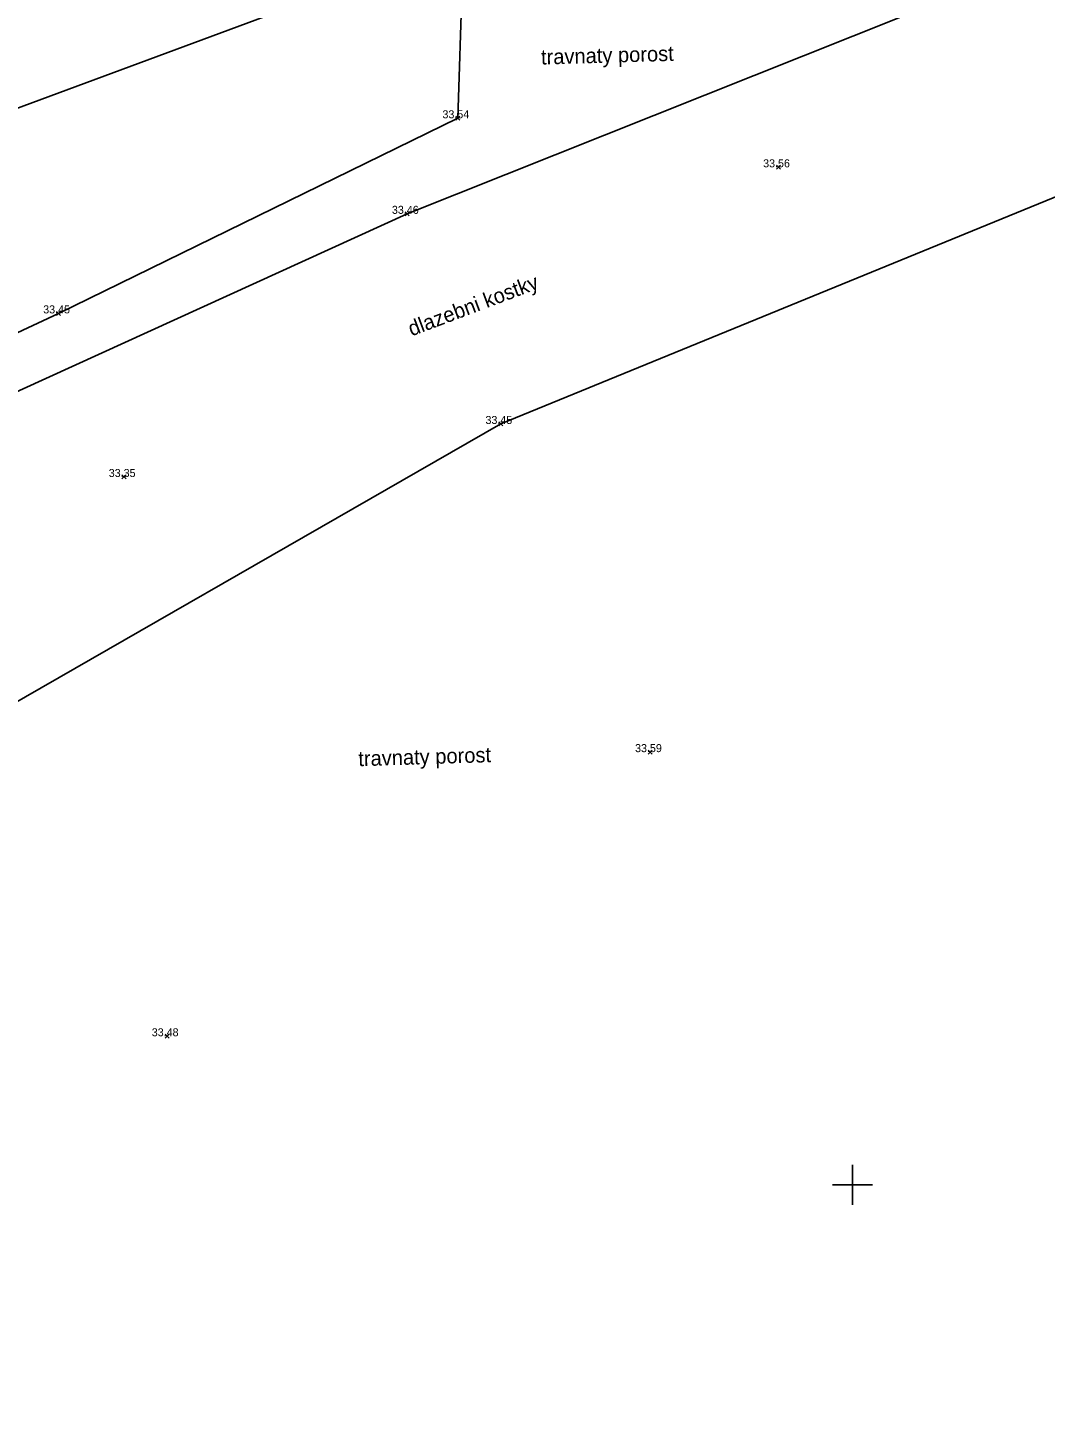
# Model space of a CAD drawing. Extents: x -772865 to -772533, y -1034366 to -1034132.
# Drawn here: x -772791.49 to -772771.14, y -1034304.37 to -1034276.87 of the extents above; entities that cross this region are included whole.
import ezdxf

# ---------------------------------------------------------------- set-up
doc = ezdxf.new("R2010")
doc.units = 0
for name, color, linetype in [('body', 7, 'Continuous'), ('KM_hranice', 7, 'Continuous'), ('mistni_popis', 7, 'Continuous'), ('oddeleni_ploch', 7, 'Continuous'), ('souradnicova_sit', 7, 'Continuous'), ('stromy_kere', 7, 'Continuous'), ('vyskove_koty', 7, 'Continuous')]:
    doc.layers.add(name, color=color, linetype=linetype)

msp = doc.modelspace()

# ---------------------------------------------------------------- linework, layer by layer
at = {"layer": 'body'}
for p, q in [((-772782.85, -1034278.72), (-772782.93, -1034278.64)), ((-772782.93, -1034278.72), (-772782.85, -1034278.64)), ((-772776.44, -1034279.7), (-772776.52, -1034279.62)), ((-772776.52, -1034279.7), (-772776.44, -1034279.62)), ((-772783.86, -1034280.63), (-772783.94, -1034280.55)), ((-772783.94, -1034280.63), (-772783.86, -1034280.55)), ((-772790.83, -1034282.62), (-772790.91, -1034282.54)), ((-772790.91, -1034282.62), (-772790.83, -1034282.54)), ((-772781.99, -1034284.83), (-772782.07, -1034284.75)), ((-772782.07, -1034284.83), (-772781.99, -1034284.75)), ((-772789.52, -1034285.89), (-772789.6, -1034285.81)), ((-772789.6, -1034285.89), (-772789.52, -1034285.81)), ((-772779, -1034291.39), (-772779.08, -1034291.31)), ((-772779.08, -1034291.39), (-772779, -1034291.31)), ((-772788.66, -1034297.07), (-772788.74, -1034296.99)), ((-772788.74, -1034297.07), (-772788.66, -1034296.99))]:
    msp.add_line(p, q, dxfattribs=at)
at = {"layer": 'KM_hranice'}
msp.add_line((-772778.45, -1034273.57), (-772798.72, -1034281.08), dxfattribs=at)
at = {"layer": 'oddeleni_ploch'}
for points in [[(-772569.67, -1034207.72), (-772578.35, -1034211.18), (-772588.33, -1034216.15), (-772592.11, -1034217.46), (-772598.89, -1034219.1), (-772610.21, -1034219.57), (-772621.14, -1034219.48), (-772637.34, -1034221.06), (-772647.54, -1034222.08), (-772674.34, -1034233.24), (-772685.01, -1034239.21), (-772697.33, -1034242.95), (-772712.12, -1034249.56), (-772725.85, -1034254.8), (-772738.85, -1034261.98), (-772750.37, -1034267.76), (-772764, -1034272.65), (-772783.9, -1034280.59), (-772796.38, -1034286.28), (-772810.31, -1034291.67), (-772823.61, -1034294.35), (-772828.52, -1034296.12), (-772827.01, -1034302.81), (-772823.23, -1034300.75)], [(-772689.63, -1034259.88), (-772704.53, -1034266.45), (-772719.18, -1034273.09), (-772731.59, -1034278.63), (-772738.33, -1034281.57), (-772742.46, -1034279.19), (-772747.03, -1034275.55), (-772755.44, -1034275.22), (-772763.58, -1034277.24), (-772782.03, -1034284.79), (-772793.82, -1034291.56), (-772799.88, -1034296.39), (-772802.42, -1034299.52), (-772804.8, -1034304.37)]]:
    msp.add_lwpolyline(points, dxfattribs=at)
at = {"layer": 'souradnicova_sit'}
for p, q in [((-772775, -1034299.6), (-772775, -1034300.4)), ((-772775.4, -1034300), (-772774.6, -1034300))]:
    msp.add_line(p, q, dxfattribs=at)
at = {"layer": 'stromy_kere'}
msp.add_lwpolyline([(-772697.8, -1034241.28), (-772703.73, -1034242.07), (-772708.05, -1034246.5), (-772725.99, -1034253.12), (-772730.64, -1034252.64), (-772736.35, -1034255.43), (-772738.23, -1034258.84), (-772742.19, -1034258.97), (-772751.86, -1034263.8), (-772757.95, -1034266.78), (-772758.48, -1034269.42), (-772764.72, -1034271.25), (-772777.99, -1034275.49), (-772780.54, -1034274.19), (-772782.8, -1034275.98), (-772782.89, -1034278.68), (-772790.87, -1034282.58), (-772810.31, -1034291.67)], dxfattribs=at)

# ---------------------------------------------------------------- texts
at = {"layer": 'mistni_popis'}
for s, rotation, p in [('travnaty porost', 1.6043, (-772781.221, -1034277.606)), ('dlazebni kostky', 20.6265, (-772783.813, -1034283.041)), ('travnaty porost', 1.7762, (-772784.872, -1034291.632))]:
    msp.add_text(s, height=0.3, rotation=rotation, dxfattribs=at).set_placement(p)
at = {"layer": 'vyskove_koty'}
for s, p in [('33.54', (-772783.195, -1034278.68)), ('33.56', (-772776.785, -1034279.66)), ('33.46', (-772784.205, -1034280.59)), ('33.45', (-772791.175, -1034282.58)), ('33.45', (-772782.335, -1034284.79)), ('33.35', (-772789.865, -1034285.85)), ('33.59', (-772779.345, -1034291.35)), ('33.48', (-772789.005, -1034297.03))]:
    msp.add_text(s, height=0.16, dxfattribs=at).set_placement(p)

doc.saveas('drawing.dxf')
